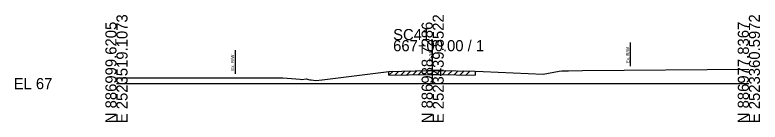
# Model space of a CAD drawing. Extents: x -26 to 183, y -10 to 24021.
# Drawn here: x -25.7 to 162.8, y 990.3 to 1017.3 of the extents above; entities that cross this region are included whole.
import ezdxf

# ---------------------------------------------------------------- set-up
doc = ezdxf.new("R2010")
doc.units = 0
for name, color, linetype in [('RD_GPK_XS_Cell', 7, 'Continuous'), ('RD_XS_ExGround', 7, 'Continuous'), ('RD_XS_ExPaveRet', 7, 'Continuous'), ('RD_XS_ExRW', 7, 'Continuous'), ('RD_XS_TX_Elev_EX', 7, 'Continuous')]:
    doc.layers.add(name, color=color, linetype=linetype)

msp = doc.modelspace()

# ---------------------------------------------------------------- linework, layer by layer
at = {"layer": 'RD_GPK_XS_Cell'}
for p, q in [((80, 1000), (80, 1010.97)), ((0, 1000), (80, 1000)), ((80, 1000), (160, 1000))]:
    msp.add_line(p, q, dxfattribs=at)
at = {"layer": 'RD_XS_ExGround'}
for p, q in [((52.03, 1000.97), (68.95, 1003.09)), ((68.95, 1003.09), (78.85, 1003.32)), ((78.85, 1003.32), (80.04, 1003.34)), ((80.04, 1003.34), (81.21, 1003.32)), ((81.21, 1003.32), (90.73, 1003.16)), ((90.73, 1003.16), (92.75, 1003.09)), ((92.75, 1003.09), (107.92, 1002.42)), ((107.92, 1002.42), (111.98, 1003.1)), ((111.98, 1003.1), (112.72, 1003.2)), ((112.72, 1003.2), (114.39, 1003.24)), ((114.39, 1003.24), (117.88, 1003.27)), ((117.88, 1003.27), (160, 1003.66)), ((0, 1001.48), (16.68, 1001.46)), ((16.68, 1001.46), (26.11, 1001.5)), ((26.11, 1001.5), (36.18, 1001.43)), ((36.18, 1001.43), (42.07, 1001.43)), ((42.07, 1001.43), (46.48, 1001.13)), ((46.48, 1001.13), (46.87, 1001.08)), ((46.87, 1001.08), (47.98, 1001.23)), ((47.98, 1001.23), (48.91, 1000.98)), ((48.91, 1000.98), (49.24, 1000.98)), ((49.24, 1000.98), (50.42, 1000.78)), ((50.42, 1000.78), (52.03, 1000.97))]:
    msp.add_line(p, q, dxfattribs=at)
at = {"layer": 'RD_XS_ExPaveRet'}
for p, q in [((68.95, 1002.09), (69.97, 1003.11)), ((68.95, 1002.09), (68.95, 1003.09)), ((70.45, 1002.13), (71.47, 1003.15)), ((71.95, 1002.16), (72.97, 1003.18)), ((73.45, 1002.19), (74.47, 1003.22)), ((74.95, 1002.23), (75.97, 1003.25)), ((76.45, 1002.26), (77.47, 1003.28)), ((77.95, 1002.29), (78.97, 1003.32)), ((79.45, 1002.33), (80.45, 1003.34)), ((80.95, 1002.33), (81.93, 1003.31)), ((82.45, 1002.3), (83.43, 1003.29)), ((83.95, 1002.28), (84.93, 1003.26)), ((85.45, 1002.25), (86.43, 1003.23)), ((86.95, 1002.22), (87.93, 1003.21)), ((88.45, 1002.2), (89.43, 1003.18)), ((90.73, 1003.16), (90.73, 1002.16)), ((68.95, 1002.09), (78.85, 1002.32)), ((78.85, 1002.32), (80.04, 1002.34)), ((80.04, 1002.34), (81.21, 1002.32)), ((81.21, 1002.32), (90.73, 1002.16))]:
    msp.add_line(p, q, dxfattribs=at)
at = {"layer": 'RD_XS_ExRW'}
for p, q in [((130, 1010.38), (130, 1004.38)), ((30, 1008.47), (30, 1002.47))]:
    msp.add_line(p, q, dxfattribs=at)

# ---------------------------------------------------------------- texts
at = {"layer": 'RD_GPK_XS_Cell'}
for s, p in [('E 2523519.1073', (2.8, 990)), ('E 2523439.8522', (82.8, 990)), ('E 2523360.5972', (162.8, 990)), ('N 886999.6205', (0, 990)), ('N 886988.7286', (80, 990)), ('N 886977.8367', (160, 990))]:
    msp.add_text(s, height=2.8, rotation=90, dxfattribs=at).set_placement(p)
for s, p in [('SC41', (70, 1010.97)), ('667+00.00 / 1', (70, 1008.17)), ('EL 67', (-26, 998.6))]:
    msp.add_text(s, height=2.8, dxfattribs=at).set_placement(p)
at = {"layer": 'RD_XS_ExRW'}
for p in [(129.75, 1005.17), (29.75, 1003.26)]:
    msp.add_text('Ex. R/W ', height=0.8, rotation=90, dxfattribs=at).set_placement(p)
at = {"layer": 'RD_XS_TX_Elev_EX'}
msp.add_text('70.34', height=0.8, rotation=90, dxfattribs=at).set_placement((79.9, 1005.34))

doc.saveas('drawing.dxf')
